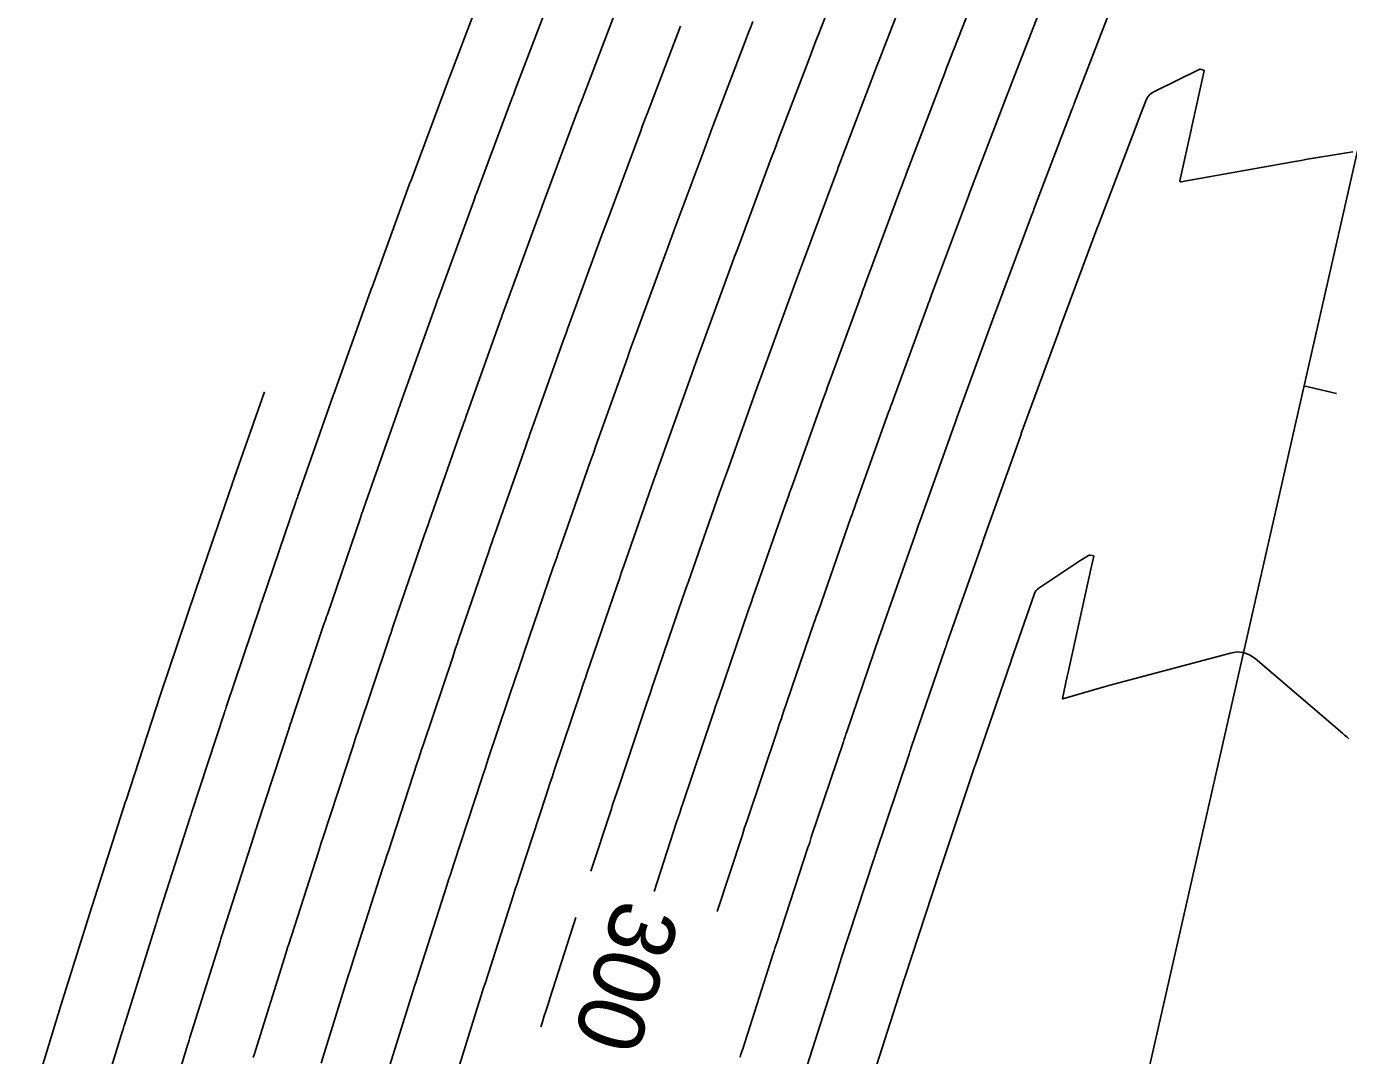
# Model space of a CAD drawing. Extents: x 1710723 to 1713003, y 548603 to 551142.
# Drawn here: x 1712241.3 to 1712360.5, y 550050.1 to 550142.9 of the extents above; entities that cross this region are included whole.
import ezdxf

# ---------------------------------------------------------------- set-up
doc = ezdxf.new("R2010")
doc.units = 0
for name, color, linetype in [('R_Contour Annot', 7, 'Continuous'), ('R_Contours', 7, 'Continuous'), ('R_Horz Alg', 7, 'Continuous'), ('R_Horz Alg Annot', 7, 'Continuous')]:
    doc.layers.add(name, color=color, linetype=linetype)

msp = doc.modelspace()

# ---------------------------------------------------------------- linework, layer by layer
at = {"layer": 'R_Contours'}
for points in [[(1712279.69, 550047.11), (1712281.96, 550054.37), (1712282.14, 550054.95), (1712282.33, 550055.53), (1712282.51, 550056.11), (1712282.7, 550056.68), (1712285.02, 550063.93), (1712285.2, 550064.51), (1712285.39, 550065.09), (1712285.58, 550065.67), (1712285.77, 550066.24), (1712288.14, 550073.48), (1712288.33, 550074.05), (1712288.52, 550074.63), (1712288.71, 550075.21), (1712288.91, 550075.79), (1712291.33, 550083), (1712291.52, 550083.58), (1712291.72, 550084.16), (1712291.91, 550084.74), (1712292.11, 550085.32), (1712294.58, 550092.51), (1712294.78, 550093.09), (1712294.98, 550093.68), (1712295.18, 550094.26), (1712295.39, 550094.84), (1712297.89, 550102), (1712298.1, 550102.59), (1712298.31, 550103.17), (1712298.52, 550103.76), (1712298.73, 550104.35), (1712301.28, 550111.48), (1712301.49, 550112.07), (1712301.7, 550112.66), (1712301.92, 550113.25), (1712302.13, 550113.83), (1712304.73, 550120.96), (1712304.95, 550121.54), (1712305.16, 550122.13), (1712305.38, 550122.71), (1712305.6, 550123.29), (1712308.26, 550130.42), (1712308.47, 550131), (1712308.69, 550131.58), (1712308.91, 550132.16), (1712309.13, 550132.74), (1712311.85, 550139.88), (1712312.07, 550140.45), (1712312.28, 550141.02), (1712312.5, 550141.59), (1712312.73, 550142.16), (1712315.5, 550149.31)], [(1712282.98, 550147.55), (1712279.49, 550138.37), (1712279.46, 550138.3), (1712279.43, 550138.22), (1712279.4, 550138.15), (1712279.38, 550138.08), (1712275.97, 550128.94), (1712275.93, 550128.85), (1712275.9, 550128.77), (1712275.87, 550128.69), (1712275.84, 550128.61), (1712272.51, 550119.48), (1712272.48, 550119.39), (1712272.44, 550119.3), (1712272.41, 550119.21), (1712272.38, 550119.12), (1712269.12, 550110.01), (1712269.08, 550109.92), (1712269.05, 550109.82), (1712269.01, 550109.72), (1712268.98, 550109.62), (1712265.79, 550100.52), (1712265.76, 550100.42), (1712265.72, 550100.32), (1712265.68, 550100.22), (1712265.65, 550100.11), (1712262.53, 550091.02), (1712262.49, 550090.92), (1712262.46, 550090.81), (1712262.42, 550090.7), (1712262.38, 550090.59), (1712259.34, 550081.51), (1712259.3, 550081.39), (1712259.26, 550081.28), (1712259.22, 550081.16), (1712259.18, 550081.04), (1712256.21, 550071.98), (1712256.17, 550071.86), (1712256.13, 550071.73), (1712256.09, 550071.61), (1712256.05, 550071.49), (1712253.15, 550062.44), (1712253.11, 550062.3), (1712253.07, 550062.17), (1712253.03, 550062.04), (1712252.99, 550061.91), (1712250.16, 550052.88), (1712250.11, 550052.74), (1712250.07, 550052.6), (1712250.03, 550052.46), (1712249.98, 550052.32), (1712247.23, 550043.3)], [(1712321.45, 550148.22), (1712318.49, 550140.61), (1712318.31, 550140.15), (1712318.14, 550139.69), (1712317.96, 550139.23), (1712317.78, 550138.77), (1712314.9, 550131.19), (1712314.72, 550130.72), (1712314.54, 550130.25), (1712314.37, 550129.78), (1712314.19, 550129.31), (1712311.37, 550121.75), (1712311.19, 550121.28), (1712311.01, 550120.8), (1712310.84, 550120.32), (1712310.66, 550119.84), (1712307.91, 550112.3), (1712307.73, 550111.82), (1712307.55, 550111.33), (1712307.38, 550110.84), (1712307.2, 550110.36), (1712304.51, 550102.83), (1712304.33, 550102.34), (1712304.16, 550101.85), (1712303.98, 550101.35), (1712303.81, 550100.86), (1712301.18, 550093.35), (1712301.01, 550092.85), (1712300.83, 550092.35), (1712300.66, 550091.84), (1712300.48, 550091.34), (1712297.92, 550083.85), (1712297.74, 550083.34), (1712297.57, 550082.83), (1712297.4, 550082.32), (1712297.22, 550081.81), (1712294.72, 550074.34), (1712294.54, 550073.82), (1712294.37, 550073.3), (1712294.2, 550072.79), (1712294.03, 550072.27), (1712292.21, 550066.72)], [(1712327.39, 550147.12), (1712324.25, 550139.05), (1712324.12, 550138.71), (1712323.99, 550138.36), (1712323.85, 550138.02), (1712323.72, 550137.67), (1712320.67, 550129.64), (1712320.53, 550129.28), (1712320.39, 550128.92), (1712320.26, 550128.56), (1712320.12, 550128.2), (1712317.14, 550120.21), (1712317, 550119.84), (1712316.87, 550119.47), (1712316.73, 550119.1), (1712316.59, 550118.72), (1712313.68, 550110.77), (1712313.54, 550110.38), (1712313.41, 550110), (1712313.27, 550109.62), (1712313.13, 550109.23), (1712310.29, 550101.3), (1712310.15, 550100.91), (1712310.01, 550100.52), (1712309.87, 550100.12), (1712309.73, 550099.73), (1712306.96, 550091.83), (1712306.82, 550091.42), (1712306.68, 550091.02), (1712306.54, 550090.61), (1712306.4, 550090.21), (1712303.7, 550082.33), (1712303.56, 550081.92), (1712303.42, 550081.5), (1712303.28, 550081.09), (1712303.14, 550080.68), (1712300.5, 550072.82), (1712300.36, 550072.4), (1712300.22, 550071.98), (1712300.08, 550071.55), (1712299.94, 550071.13), (1712297.9, 550064.9)], [(1712288.75, 550146), (1712285.42, 550137.25), (1712285.35, 550137.07), (1712285.28, 550136.9), (1712285.22, 550136.72), (1712285.15, 550136.54), (1712281.89, 550127.81), (1712281.82, 550127.63), (1712281.76, 550127.44), (1712281.69, 550127.26), (1712281.62, 550127.07), (1712278.43, 550118.35), (1712278.36, 550118.16), (1712278.29, 550117.97), (1712278.23, 550117.78), (1712278.16, 550117.59), (1712275.04, 550108.88), (1712274.97, 550108.68), (1712274.9, 550108.49), (1712274.83, 550108.29), (1712274.76, 550108.1), (1712271.71, 550099.39), (1712271.64, 550099.19), (1712271.57, 550098.99), (1712271.5, 550098.79), (1712271.43, 550098.59), (1712268.45, 550089.88), (1712268.38, 550089.68), (1712268.31, 550089.48), (1712268.24, 550089.27), (1712268.17, 550089.07), (1712265.25, 550080.36), (1712265.18, 550080.16), (1712265.11, 550079.95), (1712265.04, 550079.74), (1712264.98, 550079.53), (1712262.12, 550070.83), (1712262.05, 550070.62), (1712261.98, 550070.4), (1712261.91, 550070.19), (1712261.84, 550069.97), (1712259.06, 550061.29), (1712258.99, 550061.07), (1712258.92, 550060.85), (1712258.85, 550060.63), (1712258.78, 550060.4), (1712256.06, 550051.72), (1712255.99, 550051.5), (1712255.92, 550051.27), (1712255.85, 550051.04), (1712255.78, 550050.82), (1712253.13, 550042.15)], [(1712303.59, 550063.08), (1712305.86, 550069.99), (1712305.97, 550070.32), (1712306.07, 550070.65), (1712306.18, 550070.97), (1712306.29, 550071.3), (1712309.06, 550079.54), (1712309.16, 550079.86), (1712309.27, 550080.18), (1712309.38, 550080.49), (1712309.49, 550080.81), (1712312.32, 550089.08), (1712312.43, 550089.38), (1712312.53, 550089.69), (1712312.64, 550090), (1712312.75, 550090.3), (1712315.65, 550098.6), (1712315.76, 550098.89), (1712315.86, 550099.19), (1712315.97, 550099.48), (1712316.07, 550099.78), (1712319.05, 550108.11), (1712319.16, 550108.39), (1712319.26, 550108.67), (1712319.36, 550108.95), (1712319.46, 550109.23), (1712322.52, 550117.61), (1712322.62, 550117.87), (1712322.72, 550118.14), (1712322.82, 550118.41), (1712322.92, 550118.67), (1712326.06, 550127.09), (1712326.15, 550127.34), (1712326.24, 550127.59), (1712326.34, 550127.84), (1712326.43, 550128.1), (1712329.66, 550136.57), (1712329.75, 550136.8), (1712329.84, 550137.03), (1712329.93, 550137.27), (1712330.02, 550137.5), (1712333.33, 550146.03)], [(1712261.77, 550049.94), (1712261.87, 550050.26), (1712261.97, 550050.57), (1712264.58, 550058.9), (1712264.67, 550059.21), (1712264.77, 550059.52), (1712264.87, 550059.83), (1712264.97, 550060.14), (1712267.64, 550068.46), (1712267.74, 550068.77), (1712267.83, 550069.08), (1712267.93, 550069.38), (1712268.03, 550069.69), (1712270.77, 550078.02), (1712270.87, 550078.32), (1712270.96, 550078.62), (1712271.06, 550078.92), (1712271.17, 550079.22), (1712273.96, 550087.55), (1712274.06, 550087.85), (1712274.16, 550088.15), (1712274.26, 550088.45), (1712274.36, 550088.74), (1712277.22, 550097.07), (1712277.32, 550097.37), (1712277.42, 550097.66), (1712277.53, 550097.96), (1712277.63, 550098.25), (1712280.55, 550106.57), (1712280.65, 550106.87), (1712280.75, 550107.16), (1712280.86, 550107.45), (1712280.96, 550107.75), (1712283.94, 550116.06), (1712284.04, 550116.35), (1712284.15, 550116.64), (1712284.25, 550116.94), (1712284.36, 550117.23), (1712287.4, 550125.54), (1712287.5, 550125.83), (1712287.61, 550126.11), (1712287.71, 550126.4), (1712287.82, 550126.69), (1712290.92, 550135), (1712291.03, 550135.28), (1712291.13, 550135.57), (1712291.24, 550135.85), (1712291.35, 550136.13), (1712294.52, 550144.45)], [(1712305.65, 550049.96), (1712305.73, 550050.22), (1712305.81, 550050.47), (1712305.89, 550050.72), (1712308.64, 550059.29), (1712308.72, 550059.53), (1712308.8, 550059.77), (1712308.88, 550060.02), (1712308.96, 550060.26), (1712311.77, 550068.85), (1712311.85, 550069.08), (1712311.93, 550069.32), (1712312, 550069.55), (1712312.08, 550069.78), (1712314.97, 550078.4), (1712315.05, 550078.62), (1712315.12, 550078.85), (1712315.2, 550079.07), (1712315.27, 550079.29), (1712318.24, 550087.94), (1712318.31, 550088.15), (1712318.38, 550088.36), (1712318.46, 550088.57), (1712318.53, 550088.78), (1712321.58, 550097.47), (1712321.64, 550097.67), (1712321.71, 550097.86), (1712321.78, 550098.05), (1712321.85, 550098.25), (1712324.98, 550106.99), (1712325.04, 550107.16), (1712325.11, 550107.34), (1712325.17, 550107.52), (1712325.24, 550107.7), (1712328.45, 550116.49), (1712328.51, 550116.65), (1712328.57, 550116.81), (1712328.63, 550116.97), (1712328.69, 550117.13), (1712331.99, 550125.98), (1712332.04, 550126.12), (1712332.1, 550126.27), (1712332.15, 550126.41), (1712332.2, 550126.55), (1712335.6, 550135.46), (1712335.64, 550135.58), (1712335.69, 550135.7), (1712335.74, 550135.82), (1712335.78, 550135.94), (1712339.27, 550144.94)], [(1712300.29, 550142.91), (1712297.28, 550135.01), (1712297.13, 550134.63), (1712296.99, 550134.24), (1712296.84, 550133.85), (1712296.7, 550133.46), (1712293.75, 550125.56), (1712293.6, 550125.17), (1712293.46, 550124.78), (1712293.32, 550124.39), (1712293.17, 550124), (1712290.28, 550116.1), (1712290.14, 550115.71), (1712290, 550115.32), (1712289.86, 550114.92), (1712289.72, 550114.53), (1712286.88, 550106.61), (1712286.74, 550106.22), (1712286.6, 550105.83), (1712286.47, 550105.44), (1712286.33, 550105.05), (1712283.55, 550097.11), (1712283.41, 550096.72), (1712283.28, 550096.33), (1712283.14, 550095.94), (1712283.01, 550095.55), (1712280.28, 550087.6), (1712280.15, 550087.21), (1712280.01, 550086.82), (1712279.88, 550086.43), (1712279.75, 550086.03), (1712277.08, 550078.08), (1712276.95, 550077.68), (1712276.82, 550077.29), (1712276.69, 550076.9), (1712276.56, 550076.5), (1712273.95, 550068.54), (1712273.82, 550068.14), (1712273.69, 550067.75), (1712273.56, 550067.35), (1712273.43, 550066.95), (1712270.88, 550058.98), (1712270.75, 550058.59), (1712270.62, 550058.19), (1712270.5, 550057.79), (1712270.37, 550057.39), (1712267.88, 550049.42)], [(1712273.78, 550048.27), (1712276.17, 550055.88), (1712276.32, 550056.37), (1712276.48, 550056.86), (1712276.63, 550057.35), (1712276.79, 550057.83), (1712279.22, 550065.44), (1712279.38, 550065.93), (1712279.54, 550066.42), (1712279.7, 550066.9), (1712279.86, 550067.39), (1712282.35, 550074.99), (1712282.51, 550075.48), (1712282.67, 550075.96), (1712282.83, 550076.45), (1712282.99, 550076.93), (1712285.54, 550084.52), (1712285.7, 550085), (1712285.86, 550085.49), (1712286.03, 550085.98), (1712286.2, 550086.46), (1712288.79, 550094.03), (1712288.96, 550094.52), (1712289.13, 550095), (1712289.3, 550095.49), (1712289.47, 550095.98), (1712292.11, 550103.53), (1712292.28, 550104.01), (1712292.46, 550104.5), (1712292.63, 550104.99), (1712292.8, 550105.48), (1712295.5, 550113), (1712295.67, 550113.5), (1712295.85, 550113.99), (1712296.03, 550114.48), (1712296.21, 550114.97), (1712298.95, 550122.47), (1712299.13, 550122.96), (1712299.31, 550123.46), (1712299.49, 550123.95), (1712299.68, 550124.44), (1712302.47, 550131.92), (1712302.65, 550132.42), (1712302.84, 550132.91), (1712303.03, 550133.4), (1712303.21, 550133.89), (1712306.05, 550141.36), (1712306.24, 550141.85), (1712306.43, 550142.35), (1712306.62, 550142.84), (1712306.81, 550143.33)], [(1712360.89, 550131.58), (1712357.92, 550131.1), (1712357.35, 550131), (1712356.79, 550130.91), (1712356.23, 550130.81), (1712355.67, 550130.71), (1712345.4, 550128.86), (1712345.35, 550128.86), (1712345.32, 550128.88), (1712345.3, 550128.91), (1712345.31, 550128.96), (1712346.14, 550132.76), (1712346.2, 550133.03), (1712346.26, 550133.3), (1712346.32, 550133.57), (1712346.38, 550133.85), (1712347.48, 550138.88), (1712347.48, 550138.9), (1712347.47, 550138.92), (1712347.46, 550138.94), (1712347.43, 550138.95), (1712347.13, 550139.02), (1712347.1, 550139.02), (1712347.08, 550139.02), (1712347.06, 550139.02), (1712347.04, 550139.01), (1712343.02, 550137.03), (1712342.76, 550136.87), (1712342.55, 550136.68), (1712342.37, 550136.45), (1712342.24, 550136.17), (1712341.55, 550134.39), (1712341.54, 550134.36), (1712337.97, 550125), (1712337.96, 550124.97), (1712337.95, 550124.94), (1712337.94, 550124.9), (1712337.92, 550124.87), (1712334.46, 550115.59), (1712334.44, 550115.54), (1712334.42, 550115.48), (1712334.4, 550115.43), (1712334.38, 550115.37), (1712331.01, 550106.17), (1712330.99, 550106.09), (1712330.96, 550106.01), (1712330.93, 550105.94), (1712330.9, 550105.86), (1712327.63, 550096.72), (1712327.6, 550096.62), (1712327.56, 550096.53), (1712327.53, 550096.44), (1712327.5, 550096.34), (1712324.31, 550087.25), (1712324.27, 550087.14), (1712324.24, 550087.03), (1712324.2, 550086.92), (1712324.16, 550086.81), (1712321.06, 550077.77), (1712321.02, 550077.64), (1712320.97, 550077.52), (1712320.93, 550077.39), (1712320.89, 550077.27), (1712317.87, 550068.27), (1712317.82, 550068.13), (1712317.78, 550067.99), (1712317.73, 550067.85), (1712317.69, 550067.71), (1712314.75, 550058.75), (1712314.7, 550058.6), (1712314.65, 550058.45), (1712314.6, 550058.29), (1712314.55, 550058.14), (1712311.69, 550049.21)], [(1712241.32, 550044.46), (1712244.19, 550053.83), (1712244.2, 550053.88), (1712244.22, 550053.93), (1712244.23, 550053.98), (1712244.25, 550054.03), (1712247.19, 550063.42), (1712247.2, 550063.46), (1712247.22, 550063.5), (1712247.23, 550063.54), (1712247.24, 550063.59), (1712250.26, 550073), (1712250.27, 550073.03), (1712250.28, 550073.06), (1712250.29, 550073.09), (1712250.3, 550073.13), (1712253.39, 550082.56), (1712253.4, 550082.58), (1712253.41, 550082.61), (1712253.42, 550082.63), (1712253.42, 550082.65), (1712256.59, 550092.1), (1712256.61, 550092.13), (1712256.62, 550092.17), (1712259.86, 550101.63), (1712259.87, 550101.66), (1712262.77, 550109.93)], [(1712360.53, 550078.66), (1712360.34, 550078.83), (1712360.14, 550079), (1712359.95, 550079.17), (1712352.08, 550085.89), (1712351.57, 550086.24), (1712351.03, 550086.43), (1712350.46, 550086.49), (1712349.86, 550086.39), (1712340.25, 550083.84), (1712339.81, 550083.72), (1712339.36, 550083.59), (1712338.91, 550083.47), (1712338.47, 550083.34), (1712334.76, 550082.25), (1712334.73, 550082.24), (1712334.72, 550082.25), (1712334.71, 550082.26), (1712334.71, 550082.29), (1712335.15, 550084.3), (1712335.18, 550084.42), (1712335.21, 550084.54), (1712335.23, 550084.66), (1712335.26, 550084.78), (1712337.34, 550094.21), (1712337.37, 550094.35), (1712337.54, 550095.13), (1712337.54, 550095.13), (1712337.54, 550095.14), (1712337.54, 550095.14), (1712337.54, 550095.14), (1712337.22, 550095.21), (1712337.18, 550095.22), (1712337.14, 550095.21), (1712337.1, 550095.2), (1712337.06, 550095.18), (1712336.29, 550094.7), (1712336.2, 550094.65), (1712336.11, 550094.59), (1712336.02, 550094.53), (1712335.93, 550094.47), (1712332.6, 550092.25), (1712332.47, 550092.15), (1712332.36, 550092.04), (1712332.27, 550091.9), (1712332.21, 550091.75), (1712330.1, 550085.73), (1712330.08, 550085.69), (1712330.08, 550085.68), (1712326.84, 550076.25), (1712326.83, 550076.22), (1712326.82, 550076.19), (1712326.81, 550076.16), (1712326.8, 550076.13), (1712323.66, 550066.75), (1712323.64, 550066.71), (1712323.63, 550066.66), (1712323.61, 550066.62), (1712323.6, 550066.57), (1712320.54, 550057.23), (1712320.52, 550057.18), (1712320.5, 550057.12), (1712320.48, 550057.06), (1712320.46, 550057), (1712317.48, 550047.7)], [(1712290.86, 550062.56), (1712288.51, 550055.25), (1712288.35, 550054.73), (1712288.18, 550054.2), (1712288.01, 550053.68), (1712287.85, 550053.15), (1712287.7, 550052.68)]]:
    msp.add_lwpolyline(points, dxfattribs=at)
at = {"layer": 'R_Horz Alg'}
msp.add_line((1712246.77, 549627.28), (1712450.81, 550525.82), dxfattribs=at)
at = {"layer": 'R_Horz Alg Annot'}
msp.add_lwpolyline([(1712359.42, 550109.8), (1712356.49, 550110.47)], dxfattribs=at)

# ---------------------------------------------------------------- texts
at = {"layer": 'R_Contour Annot'}
msp.add_text('300', height=6, rotation=252.2882, dxfattribs=at).set_placement((1712294.61, 550064.46))

doc.saveas('drawing.dxf')
